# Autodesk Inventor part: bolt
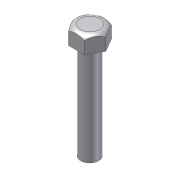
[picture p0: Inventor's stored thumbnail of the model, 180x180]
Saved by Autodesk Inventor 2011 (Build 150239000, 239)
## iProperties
Created: 2009-05
Part Number: bolt
Document SubType Name: Modeling
Designer: Sham
Density: 1 g/cm^3
Author: Sham
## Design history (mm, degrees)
sketch "Sketch1"
  geometry: L1 (4, 0)-(2, -3.464); L2 (2, -3.464)-(-2, -3.464); L3 (-2, -3.464)-(-4, 0); L4 (-4, 0)-(-2, 3.464); L5 (-2, 3.464)-(2, 3.464); L6 (2, 3.464)-(4, 0); 1 further point
  constraints: 12 end point, 13 other
  dimensions: "d0" = 8 distance of L1.start L3.end
extrude "Extrusion1" new body sketch "Sketch1" distance "d1" = 4; taper "d2" = 0 deg
sketch "Sketch2"
  geometry: C1 r 2.25 at (0.082, 0)
  constraints: 1 centre point
  dimensions: "d3" = 4.5 diameter of C1
extrude "Extrusion2" join sketch "Sketch2" distance "d4" = 25; taper "d5" = 0 deg
sketch "Sketch3"
  geometry: L1 (0, -30.841)-(0, 10.046) reference; A1 r 1.88 centre (-2.337, 2.123) between (-2.442, 4) and (-4, 3)
  constraints: 2 point on circle, 1 centre point
revolve "Revolution1" sketch "Sketch3" stored, may be unused: angle "d7" = 90 deg
body "Solid1"
other parameters: "d6" = 90 deg
